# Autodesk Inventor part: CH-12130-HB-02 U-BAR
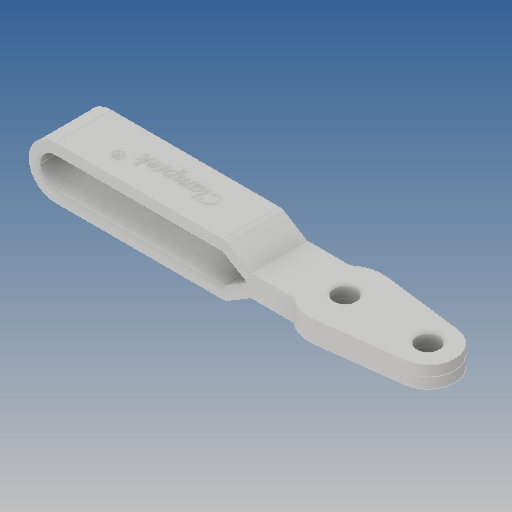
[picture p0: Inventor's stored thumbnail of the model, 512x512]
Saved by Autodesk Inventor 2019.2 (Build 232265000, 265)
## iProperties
Created: 2012-09
Part Number: CH-12130-HB-02 U-BAR
Material: Ogólny
Document SubType Name: Modeling
Designer: CADENGINEERING4
Density: 1 g/cm^3
Appearance: Domyślna
Author: CADENGINEERING4
Revision Number: ÈÎºÎ
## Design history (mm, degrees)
feature "ÇÐ³ý-À­Éì2"
feature "ÇÐ³ý-À­Éì6"
node "Bryła1"
node "Bryła2"
